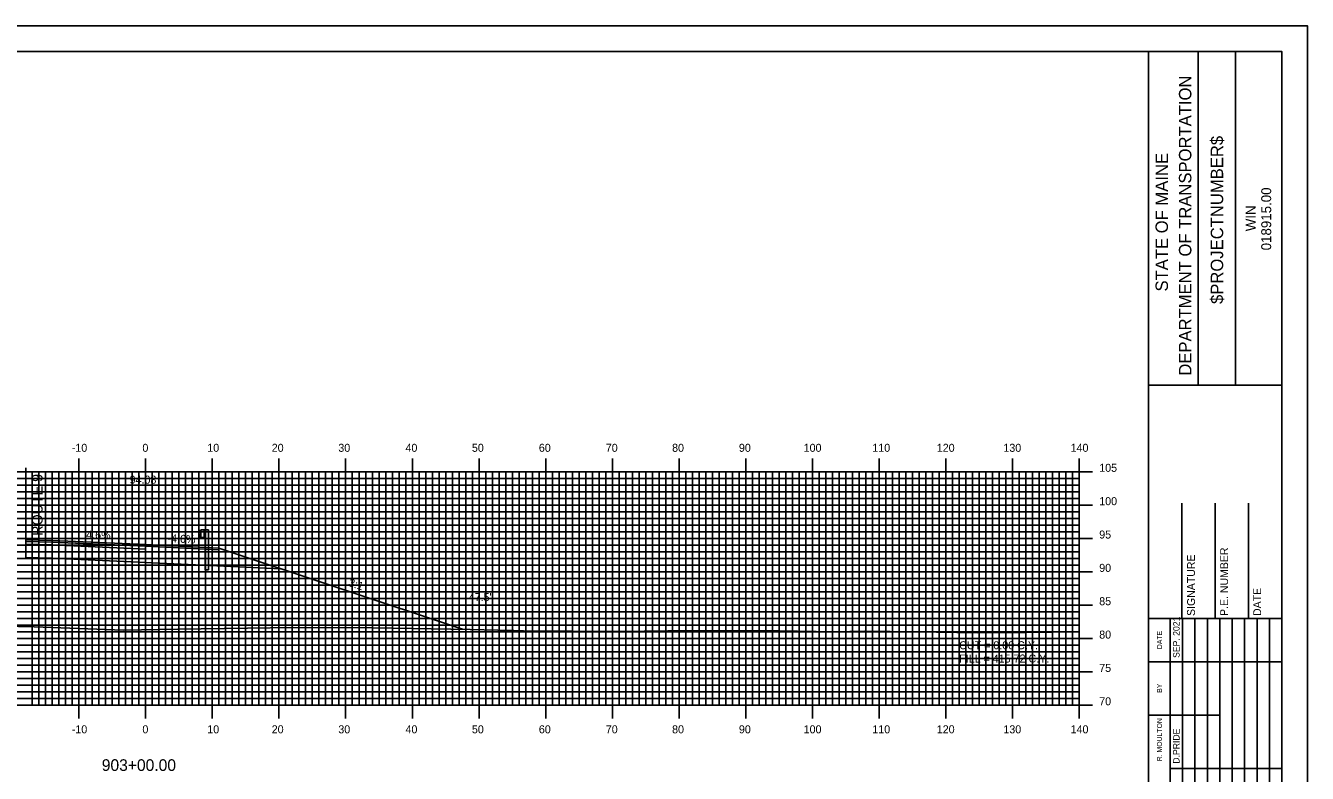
# Model space of a CAD drawing. Extents: x 856716 to 857060, y 364765 to 364985.
# Drawn here: x 856864.3 to 857056.5, y 364873.1 to 364985.2 of the extents above; entities that cross this region are included whole.
import ezdxf

# ---------------------------------------------------------------- set-up
doc = ezdxf.new("R2010")
doc.units = 0
for name, color, linetype in [('ANNOTATION', 7, 'Continuous'), ('BORDER', 7, 'Continuous'), ('D_Guardrail_Beam_Lt', 7, 'Continuous'), ('D_Roadway_Centerline_Text', 7, 'Continuous'), ('D_Roadway_Edge_Shoulder', 7, 'Continuous'), ('D_Roadway_Edge_TW', 7, 'Continuous'), ('D_Roadway_Pavement', 7, 'Continuous'), ('D_Roadway_SlopeLines', 7, 'Continuous'), ('D_Roadway_SubGrade', 7, 'Continuous'), ('D_Text_Standard', 7, 'Continuous'), ('H_V ANNOTATION', 7, 'Continuous'), ('MAJOR', 7, 'Continuous'), ('MINOR', 7, 'Continuous'), ('PLOT BOUNDARY', 7, 'Continuous'), ('S_Bridge_BoxCulvert_MultiLine', 7, 'Continuous'), ('S_Roadway_Centerline', 7, 'Continuous')]:
    doc.layers.add(name, color=color, linetype=linetype)

msp = doc.modelspace()

# ---------------------------------------------------------------- linework, layer by layer
at = {"layer": 'BORDER'}
for p, q in [((857032.68, 364771.3), (857032.68, 364981.3)), ((857040.14, 364931.3), (857040.14, 364981.3)), ((857045.73, 364931.3), (857045.73, 364981.3)), ((857032.68, 364931.29), (857052.68, 364931.29)), ((857037.68, 364896.31), (857037.68, 364913.6)), ((857042.68, 364896.31), (857042.68, 364913.6)), ((857047.68, 364896.31), (857047.68, 364913.6)), ((857032.68, 364896.31), (857052.68, 364896.31))]:
    msp.add_line(p, q, dxfattribs=at)
msp.add_lwpolyline([(856732.68, 364771.3), (857052.68, 364771.3), (857052.68, 364981.3), (856732.68, 364981.3)], close=True, dxfattribs=at)
for points in [[(857035.91, 364889.81), (857035.91, 364896.31)], [(857035.91, 364861.31), (857035.91, 364894.9)], [(857037.78, 364861.31), (857037.78, 364896.31)], [(857039.64, 364896.31), (857039.64, 364861.31)], [(857041.5, 364861.31), (857041.5, 364896.31)], [(857043.37, 364861.31), (857043.37, 364896.31)], [(857045.23, 364861.31), (857045.23, 364896.31)], [(857047.09, 364861.31), (857047.09, 364896.31)], [(857048.96, 364861.31), (857048.96, 364896.31)], [(857050.82, 364861.31), (857050.82, 364896.31)], [(857032.68, 364889.81), (857052.68, 364889.81)], [(857032.68, 364881.81), (857035.91, 364881.81)], [(857035.91, 364881.81), (857043.36, 364881.81)], [(857035.91, 364873.81), (857052.68, 364873.81)]]:
    msp.add_lwpolyline(points, dxfattribs=at)
at = {"layer": 'D_Guardrail_Beam_Lt'}
for p, q in [((856890.46, 364909.49), (856890.32, 364909.39)), ((856890.32, 364909.25), (856890.51, 364909.11)), ((856890.51, 364908.91), (856890.32, 364908.77)), ((856890.32, 364908.63), (856890.46, 364908.53)), ((856890.55, 364909.51), (856890.48, 364909.5)), ((856890.48, 364908.52), (856890.55, 364908.51)), ((856890.55, 364909.59), (856891.24, 364909.59)), ((856890.55, 364908.43), (856890.55, 364909.59)), ((856890.55, 364909.04), (856890.55, 364908.97)), ((856891.24, 364908.43), (856890.55, 364908.43)), ((856891.07, 364909.59), (856891.07, 364908.43)), ((856891.18, 364909.59), (856891.18, 364908.43)), ((856891.22, 364903.59), (856891.22, 364908.43)), ((856891.24, 364909.59), (856891.71, 364909.59)), ((856891.24, 364909.59), (856891.24, 364908.43)), ((856891.71, 364909.59), (856891.71, 364903.59)), ((856891.22, 364903.59), (856891.71, 364903.59))]:
    msp.add_line(p, q, dxfattribs=at)
for centre, major_axis, start_param, end_param in [((856890.37, 364909.32), (-0.0877, 0), 5.323254, 7.243116), ((856890.37, 364908.7), (-0.0877, 0), 5.323254, 7.243116), ((856890.49, 364909.45), (-0.0417, 0), 4.907132, 5.323254), ((856890.49, 364908.57), (-0.0417, 0), 0.959931, 1.376053), ((856890.47, 364909.04), (0.0789, 0), 0, 0.959931), ((856890.47, 364908.97), (0.0789, 0), 5.323254, 6.283185)]:
    msp.add_ellipse(centre, major_axis=major_axis, ratio=0.995501, start_param=start_param, end_param=end_param, dxfattribs=at)
at = {"layer": 'D_Roadway_Edge_Shoulder'}
for points in [[(856868.28, 364908.02), (856864.3, 364908.12), (856864.3, 364907.87), (856868.28, 364907.77)], [(856882.28, 364907.38), (856890.28, 364907.01), (856890.28, 364907.01), (856893.28, 364906.87), (856893.28, 364906.62), (856882.28, 364907.13)]]:
    msp.add_lwpolyline(points, close=True, dxfattribs=at)
at = {"layer": 'D_Roadway_Edge_TW'}
msp.add_lwpolyline([(856868.28, 364908.02), (856882.28, 364907.38), (856882.28, 364907.13), (856868.28, 364907.77)], close=True, dxfattribs=at)
msp.add_lwpolyline([(856868.28, 364908.02), (856882.28, 364907.38), (856882.28, 364907.13), (856868.28, 364907.77)], close=True, dxfattribs=at)
msp.add_lwpolyline([(856868.28, 364908.02), (856882.28, 364907.38), (856882.28, 364907.13), (856868.28, 364907.77)], close=True, dxfattribs=at)
msp.add_lwpolyline([(856868.28, 364908.02), (856868.28, 364907.77)], dxfattribs=at)
msp.add_lwpolyline([(856868.28, 364908.02), (856868.28, 364907.77)], dxfattribs=at)
at = {"layer": 'D_Roadway_Pavement'}
for points in [[(856868.28, 364907.77), (856864.3, 364907.87), (856864.3, 364907.45), (856868.28, 364907.36)], [(856868.28, 364907.77), (856882.28, 364907.13), (856882.28, 364906.71), (856868.28, 364907.36)], [(856868.28, 364907.77), (856882.28, 364907.13), (856882.28, 364906.71), (856868.28, 364907.36)], [(856868.28, 364907.77), (856882.28, 364907.13), (856882.28, 364906.71), (856868.28, 364907.36)], [(856868.28, 364907.77), (856882.28, 364907.13), (856882.28, 364906.71), (856868.28, 364907.36)]]:
    msp.add_lwpolyline(points, close=True, dxfattribs=at)
for points in [[(856868.28, 364907.77), (856868.28, 364907.36)], [(856868.28, 364907.77), (856868.28, 364907.36)], [(856868.28, 364907.77), (856868.28, 364907.36)], [(856868.28, 364907.77), (856868.28, 364907.36)], [(856882.28, 364907.13), (856882.28, 364906.71)], [(856882.28, 364907.13), (856882.28, 364906.71)], [(856882.28, 364907.13), (856882.28, 364906.71)], [(856882.28, 364907.13), (856882.28, 364906.71)], [(856882.28, 364907.13), (856882.28, 364906.71)], [(856882.28, 364907.13), (856882.28, 364906.71)], [(856882.28, 364907.13), (856882.28, 364906.71)], [(856882.28, 364907.13), (856882.28, 364906.71)]]:
    msp.add_lwpolyline(points, dxfattribs=at)
at = {"layer": 'D_Roadway_SlopeLines'}
msp.add_lwpolyline([(856893.28, 364906.87), (856929.8, 364894.7)], dxfattribs=at)
at = {"layer": 'D_Roadway_SubGrade'}
msp.add_line((856864.3, 364918.88), (856864.3, 364905.74), dxfattribs=at)
for points in [[(856868.28, 364907.36), (856864.3, 364907.45), (856864.3, 364907.87), (856864.3, 364905.45), (856868.28, 364905.36)], [(856868.28, 364907.36), (856882.28, 364906.71), (856882.28, 364904.71), (856868.28, 364905.36)], [(856882.28, 364906.71), (856882.28, 364907.13), (856893.28, 364906.62), (856893.28, 364906.87), (856902.56, 364903.78), (856882.28, 364904.71)]]:
    msp.add_lwpolyline(points, close=True, dxfattribs=at)
at = {"layer": 'MAJOR'}
for p, q in [((856872.28, 364920.31), (856872.28, 364918.3)), ((856882.28, 364920.31), (856882.28, 364918.3)), ((856892.28, 364920.31), (856892.28, 364918.3)), ((856902.28, 364920.31), (856902.28, 364918.3)), ((856912.28, 364920.31), (856912.28, 364918.3)), ((856922.28, 364920.31), (856922.28, 364918.3)), ((856932.28, 364920.31), (856932.28, 364918.3)), ((856942.28, 364920.31), (856942.28, 364918.3)), ((856952.28, 364920.31), (856952.28, 364918.3)), ((856962.28, 364920.31), (856962.28, 364918.3)), ((856972.28, 364920.31), (856972.28, 364918.3)), ((856982.28, 364920.31), (856982.28, 364918.3)), ((856992.28, 364920.31), (856992.28, 364918.3)), ((857002.28, 364920.31), (857002.28, 364918.3)), ((857012.28, 364920.31), (857012.28, 364918.3)), ((857022.28, 364920.31), (857022.28, 364918.3)), ((856742.28, 364918.3), (857022.28, 364918.3)), ((856742.28, 364918.3), (857022.28, 364918.3)), ((856872.28, 364883.3), (856872.28, 364918.3)), ((856882.28, 364883.3), (856882.28, 364918.3)), ((856892.28, 364883.3), (856892.28, 364918.3)), ((856902.28, 364883.3), (856902.28, 364918.3)), ((856912.28, 364883.3), (856912.28, 364918.3)), ((856922.28, 364883.3), (856922.28, 364918.3)), ((856932.28, 364883.3), (856932.28, 364918.3)), ((856942.28, 364883.3), (856942.28, 364918.3)), ((856952.28, 364883.3), (856952.28, 364918.3)), ((856962.28, 364883.3), (856962.28, 364918.3)), ((856972.28, 364883.3), (856972.28, 364918.3)), ((856982.28, 364883.3), (856982.28, 364918.3)), ((856992.28, 364883.3), (856992.28, 364918.3)), ((857002.28, 364883.3), (857002.28, 364918.3)), ((857012.28, 364883.3), (857012.28, 364918.3)), ((857024.29, 364918.3), (857020.28, 364918.3)), ((857022.28, 364883.3), (857022.28, 364918.3)), ((857022.28, 364883.3), (857022.28, 364918.3)), ((856742.28, 364913.3), (857022.28, 364913.3)), ((857024.29, 364913.3), (857020.28, 364913.3)), ((856742.28, 364908.3), (857022.28, 364908.3)), ((857024.29, 364908.3), (857020.28, 364908.3)), ((856742.28, 364903.3), (857022.28, 364903.3)), ((857024.29, 364903.3), (857020.28, 364903.3)), ((856742.28, 364898.3), (857022.28, 364898.3)), ((857024.29, 364898.3), (857020.28, 364898.3)), ((856742.28, 364893.3), (857022.28, 364893.3)), ((857024.29, 364893.3), (857020.28, 364893.3)), ((856742.28, 364888.3), (857022.28, 364888.3)), ((857024.29, 364888.3), (857020.28, 364888.3)), ((856742.28, 364883.3), (857022.28, 364883.3)), ((856742.28, 364883.3), (857022.28, 364883.3)), ((856872.28, 364881.3), (856872.28, 364883.3)), ((856882.28, 364881.3), (856882.28, 364883.3)), ((856892.28, 364881.3), (856892.28, 364883.3)), ((856902.28, 364881.3), (856902.28, 364883.3)), ((856912.28, 364881.3), (856912.28, 364883.3)), ((856922.28, 364881.3), (856922.28, 364883.3)), ((856932.28, 364881.3), (856932.28, 364883.3)), ((856942.28, 364881.3), (856942.28, 364883.3)), ((856952.28, 364881.3), (856952.28, 364883.3)), ((856962.28, 364881.3), (856962.28, 364883.3)), ((856972.28, 364881.3), (856972.28, 364883.3)), ((856982.28, 364881.3), (856982.28, 364883.3)), ((856992.28, 364881.3), (856992.28, 364883.3)), ((857002.28, 364881.3), (857002.28, 364883.3)), ((857012.28, 364881.3), (857012.28, 364883.3)), ((857024.29, 364883.3), (857020.28, 364883.3)), ((857022.28, 364881.3), (857022.28, 364883.3))]:
    msp.add_line(p, q, dxfattribs=at)
at = {"layer": 'MINOR'}
for p, q in [((856865.28, 364883.3), (856865.28, 364918.3)), ((856866.28, 364883.3), (856866.28, 364918.3)), ((856867.28, 364883.3), (856867.28, 364918.3)), ((856868.28, 364883.3), (856868.28, 364918.3)), ((856869.28, 364883.3), (856869.28, 364918.3)), ((856870.28, 364883.3), (856870.28, 364918.3)), ((856871.28, 364883.3), (856871.28, 364918.3)), ((856873.28, 364883.3), (856873.28, 364918.3)), ((856874.28, 364883.3), (856874.28, 364918.3)), ((856875.28, 364883.3), (856875.28, 364918.3)), ((856876.28, 364883.3), (856876.28, 364918.3)), ((856877.28, 364883.3), (856877.28, 364918.3)), ((856878.28, 364883.3), (856878.28, 364918.3)), ((856879.28, 364883.3), (856879.28, 364918.3)), ((856880.28, 364883.3), (856880.28, 364918.3)), ((856881.28, 364883.3), (856881.28, 364918.3)), ((856883.28, 364883.3), (856883.28, 364918.3)), ((856884.28, 364883.3), (856884.28, 364918.3)), ((856885.28, 364883.3), (856885.28, 364918.3)), ((856886.28, 364883.3), (856886.28, 364918.3)), ((856887.28, 364883.3), (856887.28, 364918.3)), ((856888.28, 364883.3), (856888.28, 364918.3)), ((856889.28, 364883.3), (856889.28, 364918.3)), ((856890.28, 364883.3), (856890.28, 364918.3)), ((856891.28, 364883.3), (856891.28, 364918.3)), ((856893.28, 364883.3), (856893.28, 364918.3)), ((856894.28, 364883.3), (856894.28, 364918.3)), ((856895.28, 364883.3), (856895.28, 364918.3)), ((856896.28, 364883.3), (856896.28, 364918.3)), ((856897.28, 364883.3), (856897.28, 364918.3)), ((856898.28, 364883.3), (856898.28, 364918.3)), ((856899.28, 364883.3), (856899.28, 364918.3)), ((856900.28, 364883.3), (856900.28, 364918.3)), ((856901.28, 364883.3), (856901.28, 364918.3)), ((856903.28, 364883.3), (856903.28, 364918.3)), ((856904.28, 364883.3), (856904.28, 364918.3)), ((856905.28, 364883.3), (856905.28, 364918.3)), ((856906.28, 364883.3), (856906.28, 364918.3)), ((856907.28, 364883.3), (856907.28, 364918.3)), ((856908.28, 364883.3), (856908.28, 364918.3)), ((856909.28, 364883.3), (856909.28, 364918.3)), ((856910.28, 364883.3), (856910.28, 364918.3)), ((856911.28, 364883.3), (856911.28, 364918.3)), ((856913.28, 364883.3), (856913.28, 364918.3)), ((856914.28, 364883.3), (856914.28, 364918.3)), ((856915.28, 364883.3), (856915.28, 364918.3)), ((856916.28, 364883.3), (856916.28, 364918.3)), ((856917.28, 364883.3), (856917.28, 364918.3)), ((856918.28, 364883.3), (856918.28, 364918.3)), ((856919.28, 364883.3), (856919.28, 364918.3)), ((856920.28, 364883.3), (856920.28, 364918.3)), ((856921.28, 364883.3), (856921.28, 364918.3)), ((856923.28, 364883.3), (856923.28, 364918.3)), ((856924.28, 364883.3), (856924.28, 364918.3)), ((856925.28, 364883.3), (856925.28, 364918.3)), ((856926.28, 364883.3), (856926.28, 364918.3)), ((856927.28, 364883.3), (856927.28, 364918.3)), ((856928.28, 364883.3), (856928.28, 364918.3)), ((856929.28, 364883.3), (856929.28, 364918.3)), ((856930.28, 364883.3), (856930.28, 364918.3)), ((856931.28, 364883.3), (856931.28, 364918.3)), ((856933.28, 364883.3), (856933.28, 364918.3)), ((856934.28, 364883.3), (856934.28, 364918.3)), ((856935.28, 364883.3), (856935.28, 364918.3)), ((856936.28, 364883.3), (856936.28, 364918.3)), ((856937.28, 364883.3), (856937.28, 364918.3)), ((856938.28, 364883.3), (856938.28, 364918.3)), ((856939.28, 364883.3), (856939.28, 364918.3)), ((856940.28, 364883.3), (856940.28, 364918.3)), ((856941.28, 364883.3), (856941.28, 364918.3)), ((856943.28, 364883.3), (856943.28, 364918.3)), ((856944.28, 364883.3), (856944.28, 364918.3)), ((856945.28, 364883.3), (856945.28, 364918.3)), ((856946.28, 364883.3), (856946.28, 364918.3)), ((856947.28, 364883.3), (856947.28, 364918.3)), ((856948.28, 364883.3), (856948.28, 364918.3)), ((856949.28, 364883.3), (856949.28, 364918.3)), ((856950.28, 364883.3), (856950.28, 364918.3)), ((856951.28, 364883.3), (856951.28, 364918.3)), ((856953.28, 364883.3), (856953.28, 364918.3)), ((856954.28, 364883.3), (856954.28, 364918.3)), ((856955.28, 364883.3), (856955.28, 364918.3)), ((856956.28, 364883.3), (856956.28, 364918.3)), ((856957.28, 364883.3), (856957.28, 364918.3)), ((856958.28, 364883.3), (856958.28, 364918.3)), ((856959.28, 364883.3), (856959.28, 364918.3)), ((856960.28, 364883.3), (856960.28, 364918.3)), ((856961.28, 364883.3), (856961.28, 364918.3)), ((856963.28, 364883.3), (856963.28, 364918.3)), ((856964.28, 364883.3), (856964.28, 364918.3)), ((856965.28, 364883.3), (856965.28, 364918.3)), ((856966.28, 364883.3), (856966.28, 364918.3)), ((856967.28, 364883.3), (856967.28, 364918.3)), ((856968.28, 364883.3), (856968.28, 364918.3)), ((856969.28, 364883.3), (856969.28, 364918.3)), ((856970.28, 364883.3), (856970.28, 364918.3)), ((856971.28, 364883.3), (856971.28, 364918.3)), ((856973.28, 364883.3), (856973.28, 364918.3)), ((856974.28, 364883.3), (856974.28, 364918.3)), ((856975.28, 364883.3), (856975.28, 364918.3)), ((856976.28, 364883.3), (856976.28, 364918.3)), ((856977.28, 364883.3), (856977.28, 364918.3)), ((856978.28, 364883.3), (856978.28, 364918.3)), ((856979.28, 364883.3), (856979.28, 364918.3)), ((856980.28, 364883.3), (856980.28, 364918.3)), ((856981.28, 364883.3), (856981.28, 364918.3)), ((856983.28, 364883.3), (856983.28, 364918.3)), ((856984.28, 364883.3), (856984.28, 364918.3)), ((856985.28, 364883.3), (856985.28, 364918.3)), ((856986.28, 364883.3), (856986.28, 364918.3)), ((856987.28, 364883.3), (856987.28, 364918.3)), ((856988.28, 364883.3), (856988.28, 364918.3)), ((856989.28, 364883.3), (856989.28, 364918.3)), ((856990.28, 364883.3), (856990.28, 364918.3)), ((856991.28, 364883.3), (856991.28, 364918.3)), ((856993.28, 364883.3), (856993.28, 364918.3)), ((856994.28, 364883.3), (856994.28, 364918.3)), ((856995.28, 364883.3), (856995.28, 364918.3)), ((856996.28, 364883.3), (856996.28, 364918.3)), ((856997.28, 364883.3), (856997.28, 364918.3)), ((856998.28, 364883.3), (856998.28, 364918.3)), ((856999.28, 364883.3), (856999.28, 364918.3)), ((857000.28, 364883.3), (857000.28, 364918.3)), ((857001.28, 364883.3), (857001.28, 364918.3)), ((857003.28, 364883.3), (857003.28, 364918.3)), ((857004.28, 364883.3), (857004.28, 364918.3)), ((857005.28, 364883.3), (857005.28, 364918.3)), ((857006.28, 364883.3), (857006.28, 364918.3)), ((857007.28, 364883.3), (857007.28, 364918.3)), ((857008.28, 364883.3), (857008.28, 364918.3)), ((857009.28, 364883.3), (857009.28, 364918.3)), ((857010.28, 364883.3), (857010.28, 364918.3)), ((857011.28, 364883.3), (857011.28, 364918.3)), ((857013.28, 364883.3), (857013.28, 364918.3)), ((857014.28, 364883.3), (857014.28, 364918.3)), ((857015.28, 364883.3), (857015.28, 364918.3)), ((857016.28, 364883.3), (857016.28, 364918.3)), ((857017.28, 364883.3), (857017.28, 364918.3)), ((857018.28, 364883.3), (857018.28, 364918.3)), ((857019.28, 364883.3), (857019.28, 364918.3)), ((857020.28, 364883.3), (857020.28, 364918.3)), ((857021.28, 364883.3), (857021.28, 364918.3)), ((856742.28, 364917.3), (857022.28, 364917.3)), ((856742.28, 364916.3), (857022.28, 364916.3)), ((857022.28, 364917.3), (857020.28, 364917.3)), ((857022.28, 364916.3), (857020.28, 364916.3)), ((856742.28, 364915.3), (857022.28, 364915.3)), ((856742.28, 364914.3), (857022.28, 364914.3)), ((857022.28, 364915.3), (857020.28, 364915.3)), ((857022.28, 364914.3), (857020.28, 364914.3)), ((856742.28, 364912.3), (857022.28, 364912.3)), ((857022.28, 364912.3), (857020.28, 364912.3)), ((856742.28, 364911.3), (857022.28, 364911.3)), ((856742.28, 364910.3), (857022.28, 364910.3)), ((857022.28, 364911.3), (857020.28, 364911.3)), ((857022.28, 364910.3), (857020.28, 364910.3)), ((856742.28, 364909.3), (857022.28, 364909.3)), ((857022.28, 364909.3), (857020.28, 364909.3)), ((856742.28, 364907.3), (857022.28, 364907.3)), ((857022.28, 364907.3), (857020.28, 364907.3)), ((856742.28, 364906.3), (857022.28, 364906.3)), ((856742.28, 364905.3), (857022.28, 364905.3)), ((857022.28, 364906.3), (857020.28, 364906.3)), ((857022.28, 364905.3), (857020.28, 364905.3)), ((856742.28, 364904.3), (857022.28, 364904.3)), ((857022.28, 364904.3), (857020.28, 364904.3)), ((856742.28, 364902.3), (857022.28, 364902.3)), ((856742.28, 364901.3), (857022.28, 364901.3)), ((857022.28, 364902.3), (857020.28, 364902.3)), ((857022.28, 364901.3), (857020.28, 364901.3)), ((856742.28, 364900.3), (857022.28, 364900.3)), ((856742.28, 364899.3), (857022.28, 364899.3)), ((857022.28, 364900.3), (857020.28, 364900.3)), ((857022.28, 364899.3), (857020.28, 364899.3)), ((856742.28, 364897.3), (857022.28, 364897.3)), ((857022.28, 364897.3), (857020.28, 364897.3)), ((856742.28, 364896.3), (857022.28, 364896.3)), ((856742.28, 364895.3), (857022.28, 364895.3)), ((857022.28, 364896.3), (857020.28, 364896.3)), ((857022.28, 364895.3), (857020.28, 364895.3)), ((856742.28, 364894.3), (857022.28, 364894.3)), ((857022.28, 364894.3), (857020.28, 364894.3)), ((856742.28, 364892.3), (857022.28, 364892.3)), ((856742.28, 364891.3), (857022.28, 364891.3)), ((857022.28, 364892.3), (857020.28, 364892.3)), ((857022.28, 364891.3), (857020.28, 364891.3)), ((856742.28, 364890.3), (857022.28, 364890.3)), ((856742.28, 364889.3), (857022.28, 364889.3)), ((857022.28, 364890.3), (857020.28, 364890.3)), ((857022.28, 364889.3), (857020.28, 364889.3)), ((856742.28, 364887.3), (857022.28, 364887.3)), ((857022.28, 364887.3), (857020.28, 364887.3)), ((856742.28, 364886.3), (857022.28, 364886.3)), ((856742.28, 364885.3), (857022.28, 364885.3)), ((857022.28, 364886.3), (857020.28, 364886.3)), ((857022.28, 364885.3), (857020.28, 364885.3)), ((856742.28, 364884.3), (857022.28, 364884.3)), ((857022.28, 364884.3), (857020.28, 364884.3))]:
    msp.add_line(p, q, dxfattribs=at)
at = {"layer": 'PLOT BOUNDARY'}
msp.add_lwpolyline([(856716.49, 364765.18), (857056.49, 364765.18), (857056.49, 364985.18), (856716.49, 364985.18)], close=True, dxfattribs=at)
at = {"layer": 'S_Bridge_BoxCulvert_MultiLine'}
msp.add_line((856864.3, 364907.45), (856864.3, 364905.45), dxfattribs=at)
at = {"layer": 'S_Roadway_Centerline'}
msp.add_lwpolyline([(856860.89, 364895.16), (856865.56, 364895.05), (856878.97, 364894.55), (856887.1, 364894.71), (856897.58, 364894.87), (856904.43, 364894.94), (856916.33, 364894.92), (856930.94, 364894.68), (856935.08, 364894.56), (856937.52, 364894.52), (856938.95, 364894.48), (856953.44, 364894.36), (856960.6, 364894.48), (856971.92, 364894.46), (856973.78, 364894.46), (856977.22, 364894.44), (856985.65, 364894.3), (856990.12, 364894.39), (856997.76, 364894.33), (857007.05, 364894.16), (857014.25, 364894.21), (857022.28, 364894.3)], dxfattribs=at)

# ---------------------------------------------------------------- texts
at = {"layer": 'ANNOTATION'}
for s, height, rotation, p in [('ROUTE 9', 1.6, 90, (856866.83, 364908.71)), ('4.6%', 1.2, 357.3663, (856873.36, 364908.32)), ('-4.6%', 1.2, 357.3663, (856885.54, 364907.76)), ('3:1', 1.2, 341.5651, (856912.59, 364901.22))]:
    msp.add_text(s, height=height, rotation=rotation, dxfattribs=at).set_placement(p)
at = {"layer": 'BORDER'}
for s, height, p in [('DEPARTMENT OF TRANSPORTATION', 1.8635, (857039.1, 364932.71)), ('$PROJECTNUMBER$', 1.8635, (857043.87, 364943.46)), ('STATE OF MAINE', 1.8635, (857035.59, 364945.33)), ('018915.00', 1.491, (857051.07, 364951.5)), ('WIN', 1.491, (857048.75, 364954.36)), ('P.E. NUMBER', 1.1811, (857044.6, 364896.69)), ('SIGNATURE', 1.181, (857039.64, 364896.69)), ('DATE', 1.181, (857049.56, 364896.69)), ('SEP. 2021', 0.969, (857037.33, 364890.4)), ('DATE', 0.743, (857034.69, 364891.72)), ('BY', 0.743, (857034.69, 364885.18)), ('R. MOULTON', 0.745, (857034.69, 364874.91)), ('D.PRIDE', 0.969, (857037.33, 364874.55))]:
    msp.add_text(s, height=height, rotation=90, dxfattribs=at).set_placement(p)
at = {"layer": 'D_Roadway_Centerline_Text'}
msp.add_text('94.08', height=1.2, dxfattribs=at).set_placement((856879.88, 364916.52))
at = {"layer": 'D_Text_Standard'}
for s, p in [("47.5'", (856930.73, 364898.91)), ('CUT = 0.00 C.Y.', (857004.28, 364891.7)), ('FILL = 415.72 C.Y.', (857004.28, 364889.71))]:
    msp.add_text(s, height=1.2, dxfattribs=at).set_placement(p)
at = {"layer": 'H_V ANNOTATION'}
for s, height, p in [('-10', 1.2, (856871.21, 364921.3)), ('0', 1.2, (856881.8, 364921.3)), ('10', 1.2, (856891.53, 364921.3)), ('20', 1.2, (856901.19, 364921.3)), ('30', 1.2, (856911.18, 364921.3)), ('40', 1.2, (856921.25, 364921.3)), ('50', 1.2, (856931.21, 364921.3)), ('60', 1.2, (856941.25, 364921.3)), ('70', 1.2, (856951.29, 364921.3)), ('80', 1.2, (856961.23, 364921.3)), ('90', 1.2, (856971.25, 364921.3)), ('100', 1.2, (856980.96, 364921.3)), ('110', 1.2, (856991.26, 364921.3)), ('120', 1.2, (857000.92, 364921.3)), ('130', 1.2, (857010.91, 364921.3)), ('140', 1.2, (857020.99, 364921.3)), ('105', 1.2, (857025.28, 364918.3)), ('100', 1.2, (857025.28, 364913.3)), ('95', 1.2, (857025.28, 364908.3)), ('90', 1.2, (857025.28, 364903.3)), ('85', 1.2, (857025.28, 364898.3)), ('80', 1.2, (857025.28, 364893.3)), ('75', 1.2, (857025.28, 364888.3)), ('70', 1.2, (857025.28, 364883.3)), ('-10', 1.2, (856871.21, 364879.1)), ('0', 1.2, (856881.8, 364879.1)), ('10', 1.2, (856891.53, 364879.1)), ('20', 1.2, (856901.19, 364879.1)), ('30', 1.2, (856911.18, 364879.1)), ('40', 1.2, (856921.25, 364879.1)), ('50', 1.2, (856931.21, 364879.1)), ('60', 1.2, (856941.25, 364879.1)), ('70', 1.2, (856951.29, 364879.1)), ('80', 1.2, (856961.23, 364879.1)), ('90', 1.2, (856971.25, 364879.1)), ('100', 1.2, (856980.96, 364879.1)), ('110', 1.2, (856991.26, 364879.1)), ('120', 1.2, (857000.92, 364879.1)), ('130', 1.2, (857010.91, 364879.1)), ('140', 1.2, (857020.99, 364879.1)), ('903+00.00', 1.75, (856875.71, 364873.46))]:
    msp.add_text(s, height=height, dxfattribs=at).set_placement(p)

doc.saveas('drawing.dxf')
